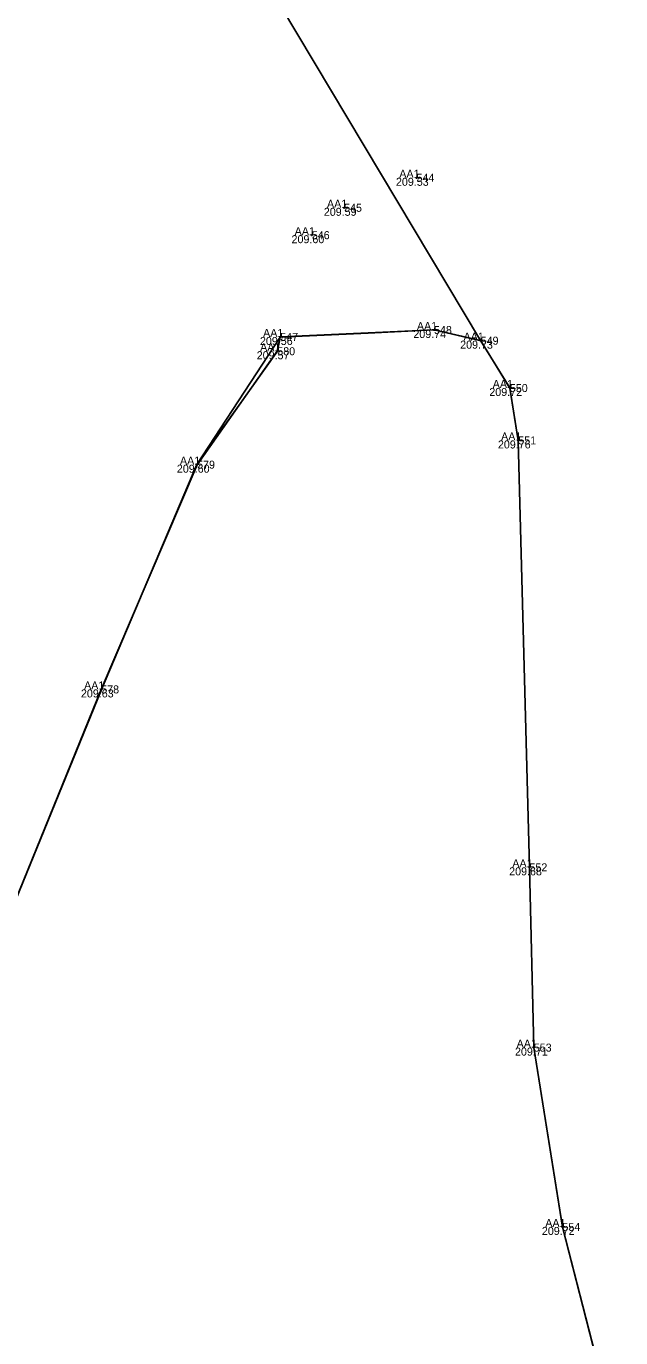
# Model space of a CAD drawing. Extents: x -262982 to -262706, y -1238714 to -1237093.
# Drawn here: x -262926.85 to -262911.98, y -1238394.45 to -1238361.66 of the extents above; entities that cross this region are included whole.
import ezdxf

# ---------------------------------------------------------------- set-up
doc = ezdxf.new("R2010")
doc.units = 0
for name, color, linetype in [('03_Asfalt', 7, 'Continuous'), ('Groma (21)', 7, 'Continuous'), ('Groma (22)', 7, 'Continuous'), ('Groma (23)', 7, 'Continuous'), ('Groma (24)', 7, 'Continuous'), ('U002_Asfalt', 7, 'Continuous'), ('U002_Zeleň_mimo', 7, 'Continuous')]:
    doc.layers.add(name, color=color, linetype=linetype)

msp = doc.modelspace()

# ---------------------------------------------------------------- linework, layer by layer
at = {"layer": '03_Asfalt'}
for points in [[(-262931.78, -1238394.73), (-262927.567, -1238384.599), (-262924.973, -1238378.239), (-262922.576, -1238372.621), (-262920.572, -1238369.785), (-262920.498, -1238369.428)], [(-262920.498, -1238369.428), (-262918.296, -1238369.328), (-262916.653, -1238369.254), (-262915.487, -1238369.521), (-262914.758, -1238370.704), (-262914.548, -1238372.015), (-262914.268, -1238382.687), (-262914.16, -1238387.193), (-262913.444, -1238391.676), (-262911.985, -1238397.337)]]:
    msp.add_lwpolyline(points, dxfattribs=at)
at = {"layer": 'Groma (21)'}
for centre in [(-262917.093, -1238365.449), (-262918.901, -1238366.199), (-262919.709, -1238366.884), (-262920.498, -1238369.428), (-262916.653, -1238369.254), (-262920.572, -1238369.785), (-262915.487, -1238369.521), (-262914.758, -1238370.704), (-262914.548, -1238372.015), (-262922.576, -1238372.621), (-262924.973, -1238378.239), (-262914.268, -1238382.687), (-262914.16, -1238387.193), (-262913.444, -1238391.676)]:
    msp.add_circle(centre, 0.01, dxfattribs=at)
at = {"layer": 'U002_Asfalt'}
msp.add_lwpolyline([(-262926.72, -1238350.73), (-262915.49, -1238369.52), (-262916.65, -1238369.25), (-262918.3, -1238369.33), (-262920.5, -1238369.43), (-262920.57, -1238369.78), (-262922.58, -1238372.62), (-262924.97, -1238378.24), (-262927.57, -1238384.6), (-262931.78, -1238394.73)], dxfattribs=at)
at = {"layer": 'U002_Zeleň_mimo'}
msp.add_lwpolyline([(-262931.78, -1238394.73), (-262927.57, -1238384.6), (-262924.97, -1238378.24), (-262922.58, -1238372.62), (-262920.5, -1238369.43), (-262918.3, -1238369.33), (-262916.65, -1238369.25), (-262915.49, -1238369.52), (-262914.76, -1238370.7), (-262914.55, -1238372.02), (-262914.27, -1238382.69), (-262914.16, -1238387.19), (-262913.44, -1238391.68), (-262911.99, -1238397.34)], dxfattribs=at)

# ---------------------------------------------------------------- texts
at = {"layer": 'Groma (22)'}
for s, p in [('544', (-262917.093, -1238365.549)), ('545', (-262918.901, -1238366.299)), ('546', (-262919.709, -1238366.984)), ('548', (-262916.653, -1238369.354)), ('547', (-262920.498, -1238369.528)), ('549', (-262915.487, -1238369.621)), ('580', (-262920.572, -1238369.885)), ('550', (-262914.758, -1238370.804)), ('551', (-262914.548, -1238372.115)), ('579', (-262922.576, -1238372.721)), ('578', (-262924.973, -1238378.339)), ('552', (-262914.268, -1238382.787)), ('553', (-262914.16, -1238387.293)), ('554', (-262913.444, -1238391.776))]:
    msp.add_text(s, height=0.2, dxfattribs=at).set_placement(p)
at = {"layer": 'Groma (23)'}
for s, p in [('209.53', (-262917.605, -1238365.649)), ('209.59', (-262919.408, -1238366.399)), ('209.60', (-262920.215, -1238367.084)), ('209.56', (-262921.005, -1238369.628)), ('209.74', (-262917.17, -1238369.454)), ('209.57', (-262921.085, -1238369.985)), ('209.73', (-262916, -1238369.721)), ('209.72', (-262915.271, -1238370.904)), ('209.76', (-262915.056, -1238372.215)), ('209.60', (-262923.082, -1238372.821)), ('209.63', (-262925.48, -1238378.439)), ('209.68', (-262914.775, -1238382.887)), ('209.71', (-262914.629, -1238387.393)), ('209.72', (-262913.957, -1238391.876))]:
    msp.add_text(s, height=0.2, dxfattribs=at).set_placement(p)
at = {"layer": 'Groma (24)'}
for p in [(-262917.521, -1238365.449), (-262919.329, -1238366.199), (-262920.137, -1238366.884), (-262917.081, -1238369.254), (-262920.926, -1238369.428), (-262915.915, -1238369.521), (-262921, -1238369.785), (-262915.186, -1238370.704), (-262914.976, -1238372.015), (-262923.004, -1238372.621), (-262925.401, -1238378.239), (-262914.696, -1238382.687), (-262914.588, -1238387.193), (-262913.872, -1238391.676)]:
    msp.add_text('AA1', height=0.2, dxfattribs=at).set_placement(p)

doc.saveas('drawing.dxf')
